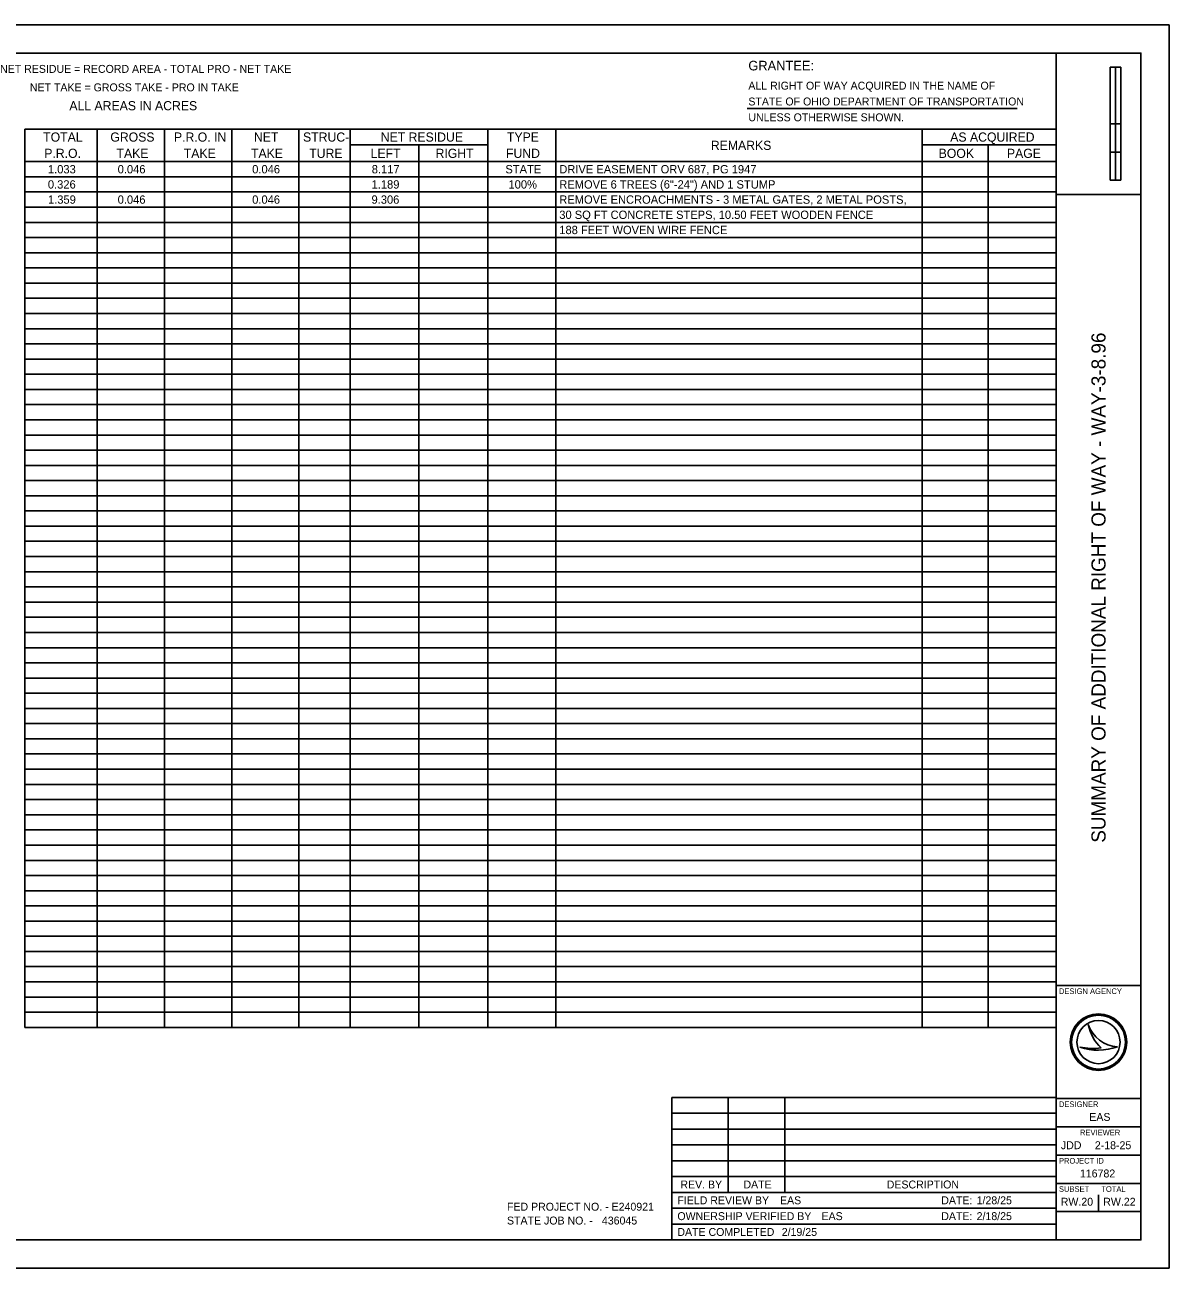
# Model space of a CAD drawing. Extents: x 0 to 34, y 0 to 22.
# Drawn here: x 13.75 to 34, y 0 to 22 of the extents above; entities that cross this region are included whole.
import ezdxf

# ---------------------------------------------------------------- set-up
doc = ezdxf.new("R2010")
doc.units = 0
for name, color, linetype in [('SH_Border', 7, 'Continuous'), ('SH_Cut_Line', 7, 'Continuous'), ('SH_Data', 7, 'Continuous'), ('SH_Text', 7, 'Continuous')]:
    doc.layers.add(name, color=color, linetype=linetype)

msp = doc.modelspace()

# ---------------------------------------------------------------- linework, layer by layer
at = {"layer": 'SH_Border'}
for p, q in [((32, 0.5), (32, 21.5)), ((32, 19), (33.5, 19)), ((32, 5), (33.5, 5)), ((32, 3), (33.5, 3)), ((32, 2.5), (33.5, 2.5)), ((32, 2), (33.5, 2)), ((32, 1.5), (33.5, 1.5)), ((32, 1), (33.5, 1))]:
    msp.add_line(p, q, dxfattribs=at)
msp.add_lwpolyline([(1.5, 21.5), (33.5, 21.5), (33.5, 0.5), (1.5, 0.5)], close=True, dxfattribs=at)
at = {"layer": 'SH_Cut_Line'}
msp.add_lwpolyline([(0, 0), (34, 0), (34, 22), (0, 22)], close=True, dxfattribs=at)
at = {"layer": 'SH_Data'}
for p, q in [((32.957, 19.25), (32.957, 21.25)), ((33.144, 21.25), (32.957, 21.25)), ((32.957, 20.25), (32.957, 21.25)), ((32.957, 21.25), (33.05, 21.25)), ((33.05, 21.25), (33.051, 21.25)), ((33.051, 21.25), (33.051, 20.25)), ((33.144, 21.25), (33.144, 19.25)), ((33.051, 20.25), (32.957, 20.25)), ((33.143, 20.25), (33.05, 20.25)), ((33.05, 20.25), (33.05, 19.75)), ((33.143, 19.75), (33.143, 20.25)), ((33.05, 19.75), (32.957, 19.75)), ((32.957, 19.75), (32.957, 19.25)), ((33.05, 19.75), (33.143, 19.75)), ((33.05, 19.25), (33.05, 19.75)), ((33.144, 19.25), (32.957, 19.25)), ((32.957, 19.25), (33.05, 19.25)), ((32.567, 4.31), (32.567, 4.31)), ((32.75, 4), (32.75, 4)), ((32.417, 3.91), (32.417, 3.91)), ((33.087, 3.919), (33.087, 3.919)), ((32.75, 1), (32.75, 1.3))]:
    msp.add_line(p, q, dxfattribs=at)
for radius in [0.5, 0.477, 0.477, 0.382]:
    msp.add_circle((32.75, 4), radius, dxfattribs=at)
for centre, radius, start, end in [((33.116, 4.498), 0.58, 198.9257, 198.9319), ((33.347, 4.47), 0.796, 191.6379, 191.6421), ((33.116, 4.498), 0.58, 198.9319, 267.1657), ((33.347, 4.47), 0.796, 191.6421, 226.0947), ((32.739, 4.87), 1.013, 251.4576, 290.0832), ((32.648, 5.154), 1.266, 259.4964, 259.4995), ((32.739, 4.87), 1.013, 251.4527, 251.4576), ((32.648, 5.154), 1.266, 259.4995, 276.6672)]:
    msp.add_arc(centre, radius, start, end, dxfattribs=at)
at = {"layer": 'SH_Text'}
for p, q in [((26.532, 20.518), (31.312, 20.518)), ((13.749, 20.156), (16.219, 20.156)), ((13.749, 20.156), (13.749, 15.817)), ((15.029, 20.156), (15.029, 15.817)), ((16.219, 20.156), (30.797, 20.156)), ((16.219, 20.156), (16.219, 15.817)), ((17.409, 20.156), (17.409, 15.817)), ((18.599, 20.156), (18.599, 15.817)), ((19.508, 20.156), (19.508, 15.817)), ((21.94, 20.156), (21.94, 15.817)), ((23.143, 20.156), (23.143, 15.817)), ((29.632, 20.156), (29.632, 15.817)), ((30.797, 20.156), (32, 20.156)), ((32, 20.156), (32, 15.817)), ((19.508, 19.875), (21.94, 19.875)), ((20.724, 19.875), (20.724, 15.817)), ((29.632, 19.875), (30.797, 19.875)), ((30.797, 19.875), (32, 19.875)), ((30.797, 19.875), (30.797, 15.817)), ((13.749, 19.58), (16.219, 19.58)), ((16.219, 19.58), (30.797, 19.58)), ((30.797, 19.58), (32, 19.58)), ((13.749, 19.311), (16.219, 19.311)), ((16.219, 19.311), (30.797, 19.311)), ((30.797, 19.311), (32, 19.311)), ((13.749, 19.043), (16.219, 19.043)), ((16.219, 19.043), (23.143, 19.043)), ((23.143, 19.043), (30.797, 19.043)), ((30.797, 19.043), (32, 19.043)), ((13.749, 18.774), (16.219, 18.774)), ((16.219, 18.774), (30.797, 18.774)), ((30.797, 18.774), (32, 18.774)), ((13.749, 18.505), (16.219, 18.505)), ((16.219, 18.505), (30.797, 18.505)), ((30.797, 18.505), (32, 18.505)), ((13.749, 18.236), (16.219, 18.236)), ((16.219, 18.236), (30.797, 18.236)), ((30.797, 18.236), (32, 18.236)), ((13.749, 17.967), (16.219, 17.967)), ((16.219, 17.967), (30.797, 17.967)), ((30.797, 17.967), (32, 17.967)), ((13.749, 17.699), (16.219, 17.699)), ((16.219, 17.699), (30.797, 17.699)), ((30.797, 17.699), (32, 17.699)), ((13.749, 17.43), (16.219, 17.43)), ((16.219, 17.43), (30.797, 17.43)), ((30.797, 17.43), (32, 17.43)), ((13.749, 17.161), (16.219, 17.161)), ((16.219, 17.161), (30.797, 17.161)), ((30.797, 17.161), (32, 17.161)), ((13.749, 16.892), (16.219, 16.892)), ((16.219, 16.892), (30.797, 16.892)), ((30.797, 16.892), (32, 16.892)), ((13.749, 16.624), (16.219, 16.624)), ((16.219, 16.624), (30.797, 16.624)), ((30.797, 16.624), (32, 16.624)), ((13.749, 16.355), (16.219, 16.355)), ((16.219, 16.355), (30.797, 16.355)), ((30.797, 16.355), (32, 16.355)), ((13.749, 16.086), (16.219, 16.086)), ((16.219, 16.086), (30.797, 16.086)), ((30.797, 16.086), (32, 16.086)), ((13.749, 15.817), (16.219, 15.817)), ((13.749, 15.817), (13.749, 15.548)), ((15.029, 15.817), (15.029, 15.548)), ((16.219, 15.817), (30.797, 15.817)), ((16.219, 15.817), (16.219, 15.548)), ((17.409, 15.817), (17.409, 15.548)), ((18.599, 15.817), (18.599, 15.548)), ((19.508, 15.817), (19.508, 15.548)), ((20.724, 15.817), (20.724, 15.548)), ((21.94, 15.817), (21.94, 15.548)), ((23.143, 15.817), (23.143, 15.548)), ((29.632, 15.817), (29.632, 15.548)), ((30.797, 15.817), (32, 15.817)), ((30.797, 15.817), (30.797, 15.548)), ((32, 15.817), (32, 15.548)), ((13.749, 15.548), (16.219, 15.548)), ((13.749, 15.548), (13.749, 15.28)), ((15.029, 15.548), (15.029, 15.28)), ((16.219, 15.548), (30.797, 15.548)), ((16.219, 15.548), (16.219, 15.28)), ((17.409, 15.548), (17.409, 15.28)), ((18.599, 15.548), (18.599, 15.28)), ((19.508, 15.548), (19.508, 15.28)), ((20.724, 15.548), (20.724, 15.28)), ((21.94, 15.548), (21.94, 15.28)), ((23.143, 15.548), (23.143, 15.28)), ((29.632, 15.548), (29.632, 15.28)), ((30.797, 15.548), (32, 15.548)), ((30.797, 15.548), (30.797, 15.28)), ((32, 15.548), (32, 15.28)), ((13.749, 15.28), (16.219, 15.28)), ((13.749, 15.28), (13.749, 15.011)), ((15.029, 15.28), (15.029, 15.011)), ((16.219, 15.28), (30.797, 15.28)), ((16.219, 15.28), (16.219, 15.011)), ((17.409, 15.28), (17.409, 15.011)), ((18.599, 15.28), (18.599, 15.011)), ((19.508, 15.28), (19.508, 15.011)), ((20.724, 15.28), (20.724, 15.011)), ((21.94, 15.28), (21.94, 15.011)), ((23.143, 15.28), (23.143, 15.011)), ((29.632, 15.28), (29.632, 15.011)), ((30.797, 15.28), (32, 15.28)), ((30.797, 15.28), (30.797, 15.011)), ((32, 15.28), (32, 15.011)), ((13.749, 15.011), (16.219, 15.011)), ((13.749, 15.011), (13.749, 14.473)), ((15.029, 15.011), (15.029, 14.473)), ((16.219, 15.011), (30.797, 15.011)), ((16.219, 15.011), (16.219, 14.473)), ((17.409, 15.011), (17.409, 14.473)), ((18.599, 15.011), (18.599, 14.473)), ((19.508, 15.011), (19.508, 14.473)), ((20.724, 15.011), (20.724, 14.473)), ((21.94, 15.011), (21.94, 14.473)), ((23.143, 15.011), (23.143, 14.473)), ((29.632, 15.011), (29.632, 14.473)), ((30.797, 15.011), (32, 15.011)), ((30.797, 15.011), (30.797, 14.473)), ((32, 15.011), (32, 14.473)), ((13.749, 14.742), (16.219, 14.742)), ((16.219, 14.742), (30.797, 14.742)), ((30.797, 14.742), (32, 14.742)), ((13.749, 14.473), (16.219, 14.473)), ((13.749, 14.473), (13.749, 14.205)), ((15.029, 14.473), (15.029, 14.205)), ((16.219, 14.473), (30.797, 14.473)), ((16.219, 14.473), (16.219, 14.205)), ((17.409, 14.473), (17.409, 14.205)), ((18.599, 14.473), (18.599, 14.205)), ((19.508, 14.473), (19.508, 14.205)), ((20.724, 14.473), (20.724, 14.205)), ((21.94, 14.473), (21.94, 14.205)), ((23.143, 14.473), (23.143, 14.205)), ((29.632, 14.473), (29.632, 14.205)), ((30.797, 14.473), (32, 14.473)), ((30.797, 14.473), (30.797, 14.205)), ((32, 14.473), (32, 14.205)), ((13.749, 14.205), (16.219, 14.205)), ((13.749, 14.205), (13.749, 9.635)), ((15.029, 14.205), (15.029, 9.635)), ((16.219, 14.205), (30.797, 14.205)), ((16.219, 14.205), (16.219, 9.635)), ((17.409, 14.205), (17.409, 9.635)), ((18.599, 14.205), (18.599, 9.635)), ((19.508, 14.205), (19.508, 9.635)), ((20.724, 14.205), (20.724, 9.635)), ((21.94, 14.205), (21.94, 9.635)), ((23.143, 14.205), (23.143, 9.635)), ((29.632, 14.205), (29.632, 9.635)), ((30.797, 14.205), (32, 14.205)), ((30.797, 14.205), (30.797, 9.635)), ((32, 14.205), (32, 9.635)), ((13.749, 13.936), (16.219, 13.936)), ((16.219, 13.936), (30.797, 13.936)), ((30.797, 13.936), (32, 13.936)), ((13.749, 13.667), (16.219, 13.667)), ((16.219, 13.667), (30.797, 13.667)), ((30.797, 13.667), (32, 13.667)), ((13.749, 13.398), (16.219, 13.398)), ((16.219, 13.398), (30.797, 13.398)), ((30.797, 13.398), (32, 13.398)), ((13.749, 13.129), (16.219, 13.129)), ((16.219, 13.129), (30.797, 13.129)), ((30.797, 13.129), (32, 13.129)), ((13.749, 12.861), (16.219, 12.861)), ((16.219, 12.861), (30.797, 12.861)), ((30.797, 12.861), (32, 12.861)), ((13.749, 12.592), (16.219, 12.592)), ((16.219, 12.592), (30.797, 12.592)), ((30.797, 12.592), (32, 12.592)), ((13.749, 12.323), (16.219, 12.323)), ((16.219, 12.323), (30.797, 12.323)), ((30.797, 12.323), (32, 12.323)), ((13.749, 12.054), (16.219, 12.054)), ((16.219, 12.054), (30.797, 12.054)), ((30.797, 12.054), (32, 12.054)), ((13.749, 11.786), (16.219, 11.786)), ((16.219, 11.786), (30.797, 11.786)), ((30.797, 11.786), (32, 11.786)), ((13.749, 11.517), (16.219, 11.517)), ((16.219, 11.517), (30.797, 11.517)), ((30.797, 11.517), (32, 11.517)), ((13.749, 11.248), (16.219, 11.248)), ((16.219, 11.248), (30.797, 11.248)), ((30.797, 11.248), (32, 11.248)), ((13.749, 10.979), (16.219, 10.979)), ((16.219, 10.979), (30.797, 10.979)), ((30.797, 10.979), (32, 10.979)), ((13.749, 10.71), (16.219, 10.71)), ((16.219, 10.71), (30.797, 10.71)), ((30.797, 10.71), (32, 10.71)), ((13.749, 10.442), (16.219, 10.442)), ((16.219, 10.442), (30.797, 10.442)), ((30.797, 10.442), (32, 10.442)), ((13.749, 10.173), (16.219, 10.173)), ((16.219, 10.173), (30.797, 10.173)), ((30.797, 10.173), (32, 10.173)), ((13.749, 9.904), (16.219, 9.904)), ((16.219, 9.904), (30.797, 9.904)), ((30.797, 9.904), (32, 9.904)), ((13.749, 9.635), (16.219, 9.635)), ((13.749, 9.635), (13.749, 9.367)), ((15.029, 9.635), (15.029, 9.367)), ((16.219, 9.635), (30.797, 9.635)), ((16.219, 9.635), (16.219, 9.367)), ((17.409, 9.635), (17.409, 9.367)), ((18.599, 9.635), (18.599, 9.367)), ((19.508, 9.635), (19.508, 9.367)), ((20.724, 9.635), (20.724, 9.367)), ((21.94, 9.635), (21.94, 9.367)), ((23.143, 9.635), (23.143, 9.367)), ((29.632, 9.635), (29.632, 9.367)), ((30.797, 9.635), (32, 9.635)), ((30.797, 9.635), (30.797, 9.367)), ((32, 9.635), (32, 9.367)), ((13.749, 9.367), (16.219, 9.367)), ((13.749, 9.367), (13.749, 9.098)), ((15.029, 9.367), (15.029, 9.098)), ((16.219, 9.367), (30.797, 9.367)), ((16.219, 9.367), (16.219, 9.098)), ((17.409, 9.367), (17.409, 9.098)), ((18.599, 9.367), (18.599, 9.098)), ((19.508, 9.367), (19.508, 9.098)), ((20.724, 9.367), (20.724, 9.098)), ((21.94, 9.367), (21.94, 9.098)), ((23.143, 9.367), (23.143, 9.098)), ((29.632, 9.367), (29.632, 9.098)), ((30.797, 9.367), (32, 9.367)), ((30.797, 9.367), (30.797, 9.098)), ((32, 9.367), (32, 9.098)), ((13.749, 9.098), (16.219, 9.098)), ((13.749, 9.098), (13.749, 8.291)), ((15.029, 9.098), (15.029, 8.291)), ((16.219, 9.098), (30.797, 9.098)), ((16.219, 9.098), (16.219, 8.291)), ((17.409, 9.098), (17.409, 8.291)), ((18.599, 9.098), (18.599, 8.291)), ((19.508, 9.098), (19.508, 8.291)), ((20.724, 9.098), (20.724, 8.291)), ((21.94, 9.098), (21.94, 8.291)), ((23.143, 9.098), (23.143, 8.291)), ((29.632, 9.098), (29.632, 8.291)), ((30.797, 9.098), (32, 9.098)), ((30.797, 9.098), (30.797, 8.291)), ((32, 9.098), (32, 8.291)), ((13.749, 8.829), (16.219, 8.829)), ((16.219, 8.829), (30.797, 8.829)), ((30.797, 8.829), (32, 8.829)), ((13.749, 8.56), (16.219, 8.56)), ((16.219, 8.56), (30.797, 8.56)), ((30.797, 8.56), (32, 8.56)), ((13.749, 8.291), (16.219, 8.291)), ((13.749, 8.291), (13.749, 8.023)), ((15.029, 8.291), (15.029, 8.023)), ((16.219, 8.291), (30.797, 8.291)), ((16.219, 8.291), (16.219, 8.023)), ((17.409, 8.291), (17.409, 8.023)), ((18.599, 8.291), (18.599, 8.023)), ((19.508, 8.291), (19.508, 8.023)), ((20.724, 8.291), (20.724, 8.023)), ((21.94, 8.291), (21.94, 8.023)), ((23.143, 8.291), (23.143, 8.023)), ((29.632, 8.291), (29.632, 8.023)), ((30.797, 8.291), (32, 8.291)), ((30.797, 8.291), (30.797, 8.023)), ((32, 8.291), (32, 8.023)), ((13.749, 8.023), (16.219, 8.023)), ((13.749, 8.023), (13.749, 7.754)), ((15.029, 8.023), (15.029, 7.754)), ((16.219, 8.023), (30.797, 8.023)), ((16.219, 8.023), (16.219, 7.754)), ((17.409, 8.023), (17.409, 7.754)), ((18.599, 8.023), (18.599, 7.754)), ((19.508, 8.023), (19.508, 7.754)), ((20.724, 8.023), (20.724, 7.754)), ((21.94, 8.023), (21.94, 7.754)), ((23.143, 8.023), (23.143, 7.754)), ((29.632, 8.023), (29.632, 7.754)), ((30.797, 8.023), (32, 8.023)), ((30.797, 8.023), (30.797, 7.754)), ((32, 8.023), (32, 7.754)), ((13.749, 7.754), (16.219, 7.754)), ((13.749, 7.754), (13.749, 6.948)), ((15.029, 7.754), (15.029, 6.948)), ((16.219, 7.754), (30.797, 7.754)), ((16.219, 7.754), (16.219, 6.948)), ((17.409, 7.754), (17.409, 6.948)), ((18.599, 7.754), (18.599, 6.948)), ((19.508, 7.754), (19.508, 6.948)), ((20.724, 7.754), (20.724, 6.948)), ((21.94, 7.754), (21.94, 6.948)), ((23.143, 7.754), (23.143, 6.948)), ((29.632, 7.754), (29.632, 6.948)), ((30.797, 7.754), (32, 7.754)), ((30.797, 7.754), (30.797, 6.948)), ((32, 7.754), (32, 6.948)), ((13.749, 7.485), (16.219, 7.485)), ((16.219, 7.485), (30.797, 7.485)), ((30.797, 7.485), (32, 7.485)), ((13.749, 7.216), (16.219, 7.216)), ((16.219, 7.216), (30.797, 7.216)), ((30.797, 7.216), (32, 7.216)), ((13.749, 6.948), (16.219, 6.948)), ((13.749, 6.948), (13.749, 6.679)), ((15.029, 6.948), (15.029, 6.679)), ((16.219, 6.948), (30.797, 6.948)), ((16.219, 6.948), (16.219, 6.679)), ((17.409, 6.948), (17.409, 6.679)), ((18.599, 6.948), (18.599, 6.679)), ((19.508, 6.948), (19.508, 6.679)), ((20.724, 6.948), (20.724, 6.679)), ((21.94, 6.948), (21.94, 6.679)), ((23.143, 6.948), (23.143, 6.679)), ((29.632, 6.948), (29.632, 6.679)), ((30.797, 6.948), (32, 6.948)), ((30.797, 6.948), (30.797, 6.679)), ((32, 6.948), (32, 6.679)), ((13.749, 6.679), (16.219, 6.679)), ((13.749, 6.679), (13.749, 4.26)), ((15.029, 6.679), (15.029, 4.26)), ((16.219, 6.679), (30.797, 6.679)), ((16.219, 6.679), (16.219, 4.26)), ((17.409, 6.679), (17.409, 4.26)), ((18.599, 6.679), (18.599, 4.26)), ((19.508, 6.679), (19.508, 4.26)), ((20.724, 6.679), (20.724, 4.26)), ((21.94, 6.679), (21.94, 4.26)), ((23.143, 6.679), (23.143, 4.26)), ((29.632, 6.679), (29.632, 4.26)), ((30.797, 6.679), (32, 6.679)), ((30.797, 6.679), (30.797, 4.26)), ((32, 6.679), (32, 4.26)), ((13.749, 6.41), (16.219, 6.41)), ((16.219, 6.41), (30.797, 6.41)), ((30.797, 6.41), (32, 6.41)), ((13.749, 6.141), (16.219, 6.141)), ((16.219, 6.141), (30.797, 6.141)), ((30.797, 6.141), (32, 6.141)), ((13.749, 5.872), (16.219, 5.872)), ((16.219, 5.872), (30.797, 5.872)), ((30.797, 5.872), (32, 5.872)), ((13.749, 5.604), (16.219, 5.604)), ((16.219, 5.604), (30.797, 5.604)), ((30.797, 5.604), (32, 5.604)), ((13.749, 5.335), (16.219, 5.335)), ((16.219, 5.335), (30.797, 5.335)), ((30.797, 5.335), (32, 5.335)), ((13.749, 5.066), (16.219, 5.066)), ((16.219, 5.066), (30.797, 5.066)), ((30.797, 5.066), (32, 5.066)), ((13.749, 4.797), (16.219, 4.797)), ((16.219, 4.797), (30.797, 4.797)), ((30.797, 4.797), (32, 4.797)), ((13.749, 4.529), (16.219, 4.529)), ((16.219, 4.529), (30.797, 4.529)), ((30.797, 4.529), (32, 4.529)), ((13.749, 4.26), (16.219, 4.26)), ((16.219, 4.26), (30.797, 4.26)), ((30.797, 4.26), (32, 4.26)), ((25.197, 3.02), (25.197, 0.5)), ((25.197, 3.02), (32, 3.02)), ((26.197, 3.02), (26.197, 1.34)), ((27.197, 3.02), (27.197, 1.34)), ((25.197, 2.74), (32, 2.74)), ((25.197, 2.46), (32, 2.46)), ((25.197, 2.18), (32, 2.18)), ((25.197, 1.9), (32, 1.9)), ((25.197, 1.62), (32, 1.62)), ((25.197, 1.34), (32, 1.34)), ((25.197, 1.06), (32, 1.06)), ((25.197, 0.78), (32, 0.78)), ((32, 0.5), (32, 0.5))]:
    msp.add_line(p, q, dxfattribs=at)

# ---------------------------------------------------------------- texts
at = {"layer": 'SH_Data'}
msp.add_text('SUMMARY OF ADDITIONAL RIGHT OF WAY - WAY-3-8.96', height=0.25, rotation=90, dxfattribs=at).set_placement((32.875, 7.528))
for s, height, p in [('DESIGN AGENCY', 0.1, (32.05, 4.85)), ('DESIGNER', 0.1, (32.05, 2.85)), ('EAS', 0.14, (32.587, 2.605)), ('REVIEWER', 0.1, (32.422, 2.35)), ('JDD', 0.14, (32.084, 2.105)), ('2-18-25', 0.14, (32.685, 2.105)), ('PROJECT ID', 0.1, (32.05, 1.85)), ('116782', 0.14, (32.421, 1.605)), ('SUBSET', 0.1, (32.05, 1.35)), ('TOTAL', 0.1, (32.8, 1.35)), ('RW.20', 0.14, (32.082, 1.105)), ('RW.22', 0.14, (32.834, 1.105))]:
    msp.add_text(s, height=height, dxfattribs=at).set_placement(p)
at = {"layer": 'SH_Text'}
for s, height, p in [('GRANTEE:', 0.17, (26.553, 21.194)), ('NET RESIDUE = RECORD AREA - TOTAL PRO - NET TAKE', 0.14, (13.31, 21.151)), ('NET TAKE = GROSS TAKE - PRO IN TAKE', 0.14, (13.837, 20.824)), ('ALL RIGHT OF WAY ACQUIRED IN THE NAME OF', 0.14, (26.553, 20.854)), ('STATE OF OHIO DEPARTMENT OF TRANSPORTATION     ', 0.14, (26.553, 20.574)), ('ALL AREAS IN ACRES', 0.16191, (14.536, 20.489)), ('UNLESS OTHERWISE SHOWN.', 0.14, (26.553, 20.294)), ('TOTAL', 0.1619, (14.073, 19.934)), ('GROSS', 0.1619, (15.261, 19.934)), ('P.R.O. IN', 0.1619, (16.387, 19.934)), ('NET', 0.1619, (17.803, 19.934)), ('STRUC-', 0.1619, (18.672, 19.934)), ('NET RESIDUE', 0.16191, (20.047, 19.934)), ('TYPE', 0.1619, (22.281, 19.934)), ('AS ACQUIRED', 0.16191, (30.126, 19.934)), ('P.R.O.', 0.1619, (14.092, 19.646)), ('TAKE', 0.1619, (15.371, 19.646)), ('TAKE', 0.1619, (16.561, 19.646)), ('TAKE', 0.1619, (17.751, 19.646)), ('TURE', 0.1619, (18.782, 19.646)), ('LEFT', 0.1619, (19.869, 19.646)), ('RIGHT', 0.1619, (21.017, 19.646)), ('FUND', 0.1619, (22.264, 19.646)), ('REMARKS', 0.1619, (25.889, 19.787)), ('BOOK', 0.1619, (29.921, 19.646)), ('PAGE', 0.1619, (31.129, 19.646)), ('1.033', 0.1472, (14.157, 19.372)), ('0.046', 0.1472, (15.391, 19.372)), ('0.046', 0.1472, (17.772, 19.372)), ('8.117', 0.1472, (19.888, 19.372)), ('STATE', 0.1472, (22.253, 19.372)), ('DRIVE EASEMENT ORV 687, PG 1947', 0.14719, (23.207, 19.372)), ('0.326', 0.1472, (14.156, 19.103)), ('1.189', 0.1472, (19.885, 19.103)), ('100%', 0.1472, (22.308, 19.103)), ('REMOVE 6 TREES (6"-24") AND 1 STUMP', 0.14719, (23.207, 19.103)), ('1.359', 0.1472, (14.158, 18.835)), ('0.046', 0.1472, (15.391, 18.835)), ('0.046', 0.1472, (17.772, 18.835)), ('9.306', 0.1472, (19.884, 18.835)), ('REMOVE ENCROACHMENTS - 3 METAL GATES, 2 METAL POSTS,', 0.14719, (23.207, 18.835)), ('30 SQ FT CONCRETE STEPS, 10.50 FEET WOODEN FENCE', 0.14719, (23.207, 18.566)), ('188 FEET WOVEN WIRE FENCE', 0.14719, (23.207, 18.297)), ('REV. BY', 0.14, (25.35, 1.41)), ('DATE', 0.14, (26.466, 1.41)), ('DESCRIPTION', 0.14, (29.002, 1.41)), ('FED PROJECT NO. - E240921', 0.14, (22.281, 1.017)), ('FIELD REVIEW BY', 0.14, (25.297, 1.13)), ('EAS                      ', 0.14, (27.113, 1.13)), ('DATE:', 0.14, (29.967, 1.13)), ('1/28/25 ', 0.14, (30.593, 1.13)), ('STATE JOB NO. -', 0.14, (22.281, 0.772)), ('436045', 0.14, (23.961, 0.772)), ('OWNERSHIP VERIFIED BY', 0.14, (25.297, 0.85)), ('EAS               ', 0.14, (27.848, 0.85)), ('DATE:', 0.14, (29.967, 0.85)), ('2/18/25 ', 0.14, (30.593, 0.85)), ('DATE COMPLETED', 0.14, (25.297, 0.57)), ('2/19/25                             ', 0.14, (27.144, 0.57))]:
    msp.add_text(s, height=height, dxfattribs=at).set_placement(p)

doc.saveas('drawing.dxf')
